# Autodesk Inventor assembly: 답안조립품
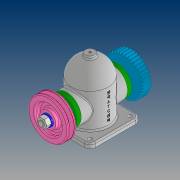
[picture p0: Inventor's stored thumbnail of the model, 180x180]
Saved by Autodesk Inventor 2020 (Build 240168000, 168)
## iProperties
Created: 2021-08
Part Number: 답안조립품
Document SubType Name: Assembly
Designer: PC312-
Author: PC312-
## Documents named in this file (14)
- C:\Users\PC312-\Desktop\710809V1004\답안조립품.iam
- C:\Users\PC312-\Desktop\710809V1004\본체.ipt
- C:\Users\PC312-\Desktop\710809V1004\베어링 6203.ipt
- C:\Users\PC312-\Desktop\710809V1004\커버.ipt
- C:\Users\PC312-\Desktop\710809V1004\축.ipt
- C:\Users\PC312-\Desktop\710809V1004\오일 실 26 38 8.ipt
- C:\Users\PC312-\Desktop\710809V1004\부시.ipt
- C:\Users\PC312-\Desktop\710809V1004\키 5x5x12.ipt
- C:\Users\PC312-\Desktop\710809V1004\볼트 M4.ipt
- C:\Users\PC312-\Desktop\710809V1004\V-벨트풀리.ipt
- V-벨트풀리.ipt
- C:\Users\PC312-\Desktop\710809V1004\스퍼기어.ipt
- C:\Users\PC312-\Desktop\710809V1004\와셔 12x24.ipt
- C:\Users\PC312-\Desktop\710809V1004\너트 M12x1.25.ipt
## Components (1 placed, 1 different names)
1. V-벨트풀리:1
